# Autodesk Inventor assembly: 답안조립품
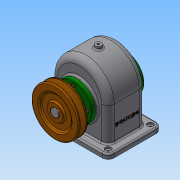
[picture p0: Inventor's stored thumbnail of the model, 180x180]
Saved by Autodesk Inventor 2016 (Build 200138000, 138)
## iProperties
Created: 2018-08
Part Number: 답안조립품
Material: 일반
Document SubType Name: Assembly
Designer: Administrator
Author: Administrator
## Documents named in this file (14)
- C:\Users\Administrator\Desktop\480811V1017\답안조립품.iam
- C:\Users\Administrator\Desktop\480811V1017\본체.ipt
- C:\Users\Administrator\Desktop\480811V1017\축.ipt
- C:\Users\Administrator\Desktop\480811V1017\베어링 6203.ipt
- C:\Users\Administrator\Desktop\480811V1017\키 6x6x22.ipt
- C:\Users\Administrator\Desktop\480811V1017\키 5x5x18.ipt
- C:\Users\Administrator\Desktop\480811V1017\스퍼기어.ipt
- C:\Users\Administrator\Desktop\480811V1017\뒤커버.ipt
- C:\Users\Administrator\Desktop\480811V1017\볼트 M4.ipt
- C:\Users\Administrator\Desktop\480811V1017\앞커버.ipt
- C:\Users\Administrator\Desktop\480811V1017\V-벨트풀리.ipt
- C:\Users\Administrator\Desktop\480811V1017\멈춤나사 M4.ipt
- C:\Users\Administrator\Desktop\480811V1017\오일 실 28 40 8.ipt
- C:\Users\Administrator\Desktop\480811V1017\부시.ipt
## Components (1 placed, 1 different names)
1. V-벨트풀리:2
